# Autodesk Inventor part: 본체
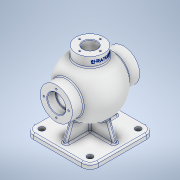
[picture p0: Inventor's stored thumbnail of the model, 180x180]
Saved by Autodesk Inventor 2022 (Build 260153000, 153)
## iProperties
Created: 2024-04
Part Number: 본체
Material: 알루미늄 6061
Document SubType Name: Modeling
Designer: Admin
Density: 2.7 g/cm^3
Appearance: 알루미늄 - 평지
Mass: 1526.72 g
Surface Area: 1173.82 cm^2
Volume: 565.453 cm^3
Author: Admin
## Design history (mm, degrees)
sketch "스케치1"
  geometry: L1 (0, 25.672)-(0, -13.488); L2 (0, 54)-(0, -54); A1 r 54 centre (0, 0) between (0, -54) and (0, 54); 3 further points
  constraints: 4 end point, 3 point on line, 2 point on circle, 2 vertical, 1 centre point, 1 coincident
  dimensions: "d0" = 54 radius of A1
revolve "회전1" sketch "스케치1" stored, may be unused: angle "d1" = 90 deg
node "작업 평면1"
sketch "스케치2"
  geometry: C1 r 31 at (0, 0); 1 further point
  constraints: 1 centre point, 1 coincident
  dimensions: "d3" = 62 diameter of C1
extrude "돌출1" join sketch "스케치2" stored distance "d4" = 10; taper "d5" = 0 deg
node "작업 평면2"
sketch "스케치3"
  geometry: C1 r 27 at (0, 0); 1 further point
  constraints: 1 centre point, 1 coincident
  dimensions: "d10" = 54 diameter of C1
extrude "돌출2" join sketch "스케치3" stored distance "d11" = 10; taper "d12" = 0 deg
node "작업 평면3"
sketch "스케치4"
  geometry: L1 (62.5, -62.5)-(-62.5, -62.5); L2 (-62.5, -62.5)-(-62.5, 62.5); L3 (-62.5, 62.5)-(62.5, 62.5); L4 (62.5, 62.5)-(62.5, -62.5); L5 (62.5, -62.5)-(-62.5, 62.5); L6 (-62.5, -62.5)-(62.5, 62.5); 1 further point
  constraints: 12 end point, 2 midpoint, 2 parallel, 1 horizontal, 1 perpendicular
  dimensions: "d14" = 125 distance of L2.end L3.end; "d15" = 125 distance of L1.end L2.end
extrude "돌출3" join sketch "스케치4" distance "d16" = 10; taper "d17" = 0 deg
sketch "스케치5"
  geometry: L1 (-50.5, 4)-(50.5, 4); L2 (50.5, 4)-(50.5, -4); L3 (50.5, -4)-(-50.5, -4); L4 (-50.5, -4)-(-50.5, 4); L5 (-50.5, 4)-(50.5, -4); L6 (50.5, 4)-(-50.5, -4); L7 (-4, -50.5)-(4, -50.5); L8 (4, -50.5)-(4, 50.5); L9 (4, 50.5)-(-4, 50.5); L10 (-4, 50.5)-(-4, -50.5); L11 (-4, -50.5)-(4, 50.5); L12 (4, -50.5)-(-4, 50.5); 5 further points
  constraints: 24 end point, 4 midpoint, 4 parallel, 2 horizontal, 2 perpendicular
  dimensions: "d18" = 101 distance of L2.end L3.end; "d19" = 8 distance of L1.end L2.end; "d20" = 8 distance of L9.end L8.end; "d21" = 101 distance of L8.end L7.end
extrude "돌출4" join sketch "스케치5" stored distance "d22" = 10; taper "d23" = 0 deg
feature "면 기울기1" dims angle "d24" = 20 deg
feature "면 기울기2" dims angle "d25" = 20 deg
feature "면 기울기3" dims angle "d26" = 20 deg
feature "면 기울기4" dims angle "d27" = 20 deg
sketch "스케치6"
  geometry: L1 (0, -44)-(0, 44); A1 r 44 centre (0, 0) between (0, -44) and (0, 44); 1 further point
  constraints: 2 end point, 2 point on circle, 1 centre point, 1 coincident, 1 midpoint, 1 vertical
  dimensions: "d28" = 44 radius of A1
revolve "회전2" sketch "스케치6" stored, may be unused: angle "d29" = 90 deg
sketch "스케치7"
  geometry: C1 r 17.5 at (0, 0); 1 further point
  constraints: 1 centre point, 1 coincident
  dimensions: "d30" = 35 diameter of C1
extrude "돌출5" cut sketch "스케치7" distance "d31" = 16; taper "d32" = 0 deg
sketch "스케치9"
  geometry: C1 r 15 at (0, 0); 1 further point
  constraints: 1 centre point, 1 coincident
  dimensions: "d39" = 30 diameter of C1
extrude "돌출7" cut sketch "스케치9" stored distance "d40" = 30; taper "d41" = 0 deg
sketch "스케치10"
  geometry: C1 r 13 at (0, 0); 1 further point
  constraints: 1 centre point, 1 coincident
  dimensions: "d45" = 26 diameter of C1
extrude "돌출8" cut sketch "스케치10" stored distance "d46" = 10; taper "d47" = 0 deg
sketch "스케치11"
  geometry: A1 r 24 centre (0, 0) between (0, 24) and (-24, 0); 3 further points
  constraints: 4 point on circle, 2 horizontal alignment, 2 vertical alignment, 1 centre point, 1 coincident
  dimensions: "d48" = 48 diameter of A1
hole "구멍1" sketch "스케치11" at (0, 24), (-24, 0), (0, -24), (24, 0) diameter "d49" = 3.242; stored, may be unused: countersink angle "d53" = 90 deg, drill point angle "d55" = 118 deg; dims "d50" = 12, "d51" = 12, "d52" = 5, "d54" = 15
sketch "스케치12"
  geometry: C1 r 27 at (0, 0) reference; A1 r 20 centre (0, 0) between (-20, 0) and (0, -20); 3 further points
  constraints: 4 point on circle, 2 horizontal alignment, 2 vertical alignment, 1 centre point, 1 coincident
  dimensions: "d59" = 40 diameter of A1
hole "구멍2" sketch "스케치12" at (-20, 0), (0, -20), (0, 20), (20, 0) diameter "d60" = 3.242; stored, may be unused: countersink angle "d64" = 90 deg, drill point angle "d66" = 118 deg; dims "d61" = 9, "d62" = 4, "d63" = 2, "d65" = 11
fillet "모깎기1" dims "d67" = 16
sketch "스케치13"
  geometry: C1 r 5.5 at (-46.5, 46.5); C2 r 5.5 at (46.5, 46.5); C3 r 5.5 at (46.5, -46.5); C4 r 5.5 at (-46.5, -46.5); A1 r 16 centre (-46.5, 46.5) between (-46.5, 62.5) and (-62.5, 46.5) reference; A2 r 16 centre (46.5, 46.5) between (62.5, 46.5) and (46.5, 62.5) reference; A3 r 16 centre (46.5, -46.5) between (46.5, -62.5) and (62.5, -46.5) reference; A4 r 16 centre (-46.5, -46.5) between (-62.5, -46.5) and (-46.5, -62.5) reference; 1 further point
  constraints: 4 centre point, 4 coincident
  dimensions: "d68" = 11 diameter of C1; "d69" = 11 diameter of C2; "d70" = 11 diameter of C3; "d71" = 11 diameter of C4
extrude "돌출9" cut sketch "스케치13" stored distance "d72" = 10; taper "d73" = 0 deg
node "작업 평면4"
sketch "스케치14"
  geometry: L1 (65, -27)-(65, 27) reference; L2 (-115, 0)-(95, 0) reference; 2 further points
  constraints: 1 point on line, 1 other
  dimensions: "d75" = 9 distance from line of L1 point (56, 0)
feature "엠보싱1" sketch "스케치14" dims "d0" = 54, "d76" = 0.5, "d77" = 0
fillet "모깎기2" dims "d78" = 3
fillet "모깎기3" dims "d79" = 3
fillet "모깎기4" dims "d80" = 3
fillet "모깎기5" dims "d81" = 3
chamfer "모따기1" distance "d82" = 1; stored, may be unused: second distance "d83" = 2, angle "d84" = 45 deg
fillet "모깎기6" dims "d85" = 0.6
node "솔리드1"
pattern_circular "원형 패턴1" dims angle "d7" = 360 deg
pattern_circular "원형 패턴2" dims angle "d37" = 360 deg
pattern_circular "원형 패턴3" dims angle "d43" = 360 deg
pattern_circular "원형 패턴4" dims angle "d57" = 360 deg
feature "A9D066F2-1C7D-4E18-AEED-F7BC21143FA4" dims "d49" = 3.242, "d50" = 12, "d51" = 12, "d52" = 5, "d53" = 90 deg, "d54" = 15, "d55" = 118 deg
other parameters: "d2" = 65, "d9" = 65, "d13" = -85, "d74" = 35
